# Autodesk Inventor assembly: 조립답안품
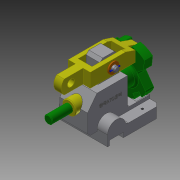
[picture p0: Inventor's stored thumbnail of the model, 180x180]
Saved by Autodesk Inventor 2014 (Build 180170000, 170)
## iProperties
Created: 2016-11
Part Number: 조립답안품
Document SubType Name: Assembly
Designer: user
Author: user
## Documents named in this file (8)
- C:\Users\user\Desktop\461108V1027\조립답안품.iam
- C:\Users\user\Desktop\461108V1027\본체.ipt
- C:\Users\user\Desktop\461108V1027\부시.ipt
- C:\Users\user\Desktop\461108V1027\분할대.ipt
- C:\Users\user\Desktop\461108V1027\분할축.ipt
- C:\Users\user\Desktop\461108V1027\와셔.ipt
- C:\Users\user\Desktop\461108V1027\원통형핀.ipt
- C:\Users\user\Desktop\461108V1027\클레비스핀.ipt
